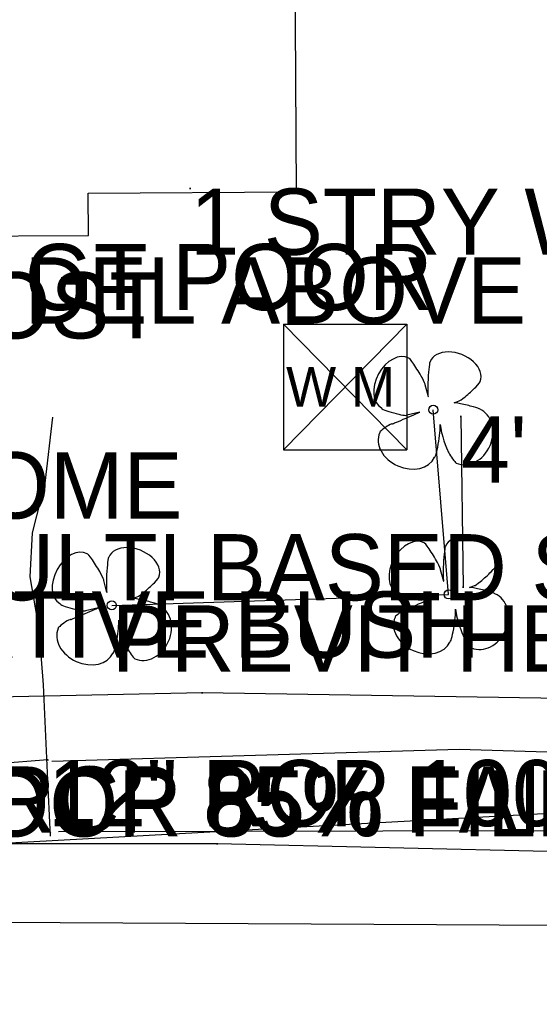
# Model space of a CAD drawing. Extents: x 1304270 to 1306561, y 1876019 to 1876752.
# Drawn here: x 1305385.4 to 1305424.7, y 1876408.6 to 1876482.3 of the extents above; entities that cross this region are included whole.
import ezdxf

# ---------------------------------------------------------------- set-up
doc = ezdxf.new("R2010")
doc.units = 0
for name, color, linetype in [('Default', 7, 'Continuous'), ('S_BUILDING', 7, 'Continuous'), ('S_BUILDING_ANNOT', 7, 'Continuous'), ('S_CROSS_DRAIN_ANNOT', 7, 'Continuous'), ('S_DITCHLINE', 7, 'Continuous'), ('S_DRG_PT_SYM', 7, 'Continuous'), ('S_EDGE_PAVEMENT', 7, 'Continuous'), ('S_FENCE', 7, 'Continuous'), ('S_FENCE_ANNOT', 7, 'Continuous'), ('S_FIBER_OPTIC_CABLE', 7, 'Continuous'), ('S_GATE_ANNOT', 7, 'Continuous'), ('S_MSC_PT_SYM', 7, 'Continuous'), ('S_SANITARY_SEWER', 7, 'Continuous'), ('S_SIDE_DRAIN', 7, 'Continuous'), ('S_SIDE_DRAIN_ANNOT', 7, 'Continuous'), ('S_SIDEWALK', 7, 'Continuous'), ('S_STR_PT_SYM', 7, 'Continuous'), ('S_SURVEY_TEXT_ANNOT', 7, 'Continuous'), ('S_TREE', 7, 'Continuous'), ('S_TREE_ANNOT', 7, 'Continuous'), ('S_UTL_PT_SYM', 7, 'Continuous'), ('S_WATER_UTILITIES', 7, 'Continuous')]:
    doc.layers.add(name, color=color, linetype=linetype)

msp = doc.modelspace()

# ---------------------------------------------------------------- linework, layer by layer
at = {"layer": 'Default'}
msp.add_line((1304873.941, 1876392.06), (1305473.534, 1876424.943), dxfattribs=at)
at = {"layer": 'S_BUILDING'}
msp.add_lwpolyline([(1305368.981, 1876540.96), (1305369.42, 1876465.829), (1305390.641, 1876465.953), (1305390.622, 1876469.145), (1305406.361, 1876469.237), (1305406.162, 1876503.401), (1305404.582, 1876503.391), (1305404.464, 1876523.501), (1305389.075, 1876523.411), (1305389.062, 1876525.646), (1305391.411, 1876525.659), (1305391.321, 1876541.09)], close=True, dxfattribs=at)
at = {"layer": 'S_DITCHLINE'}
msp.add_lwpolyline([(1305387.882, 1876426.25), (1305403.275, 1876426.705), (1305418.668, 1876427.159), (1305432.814, 1876426.73), (1305446.961, 1876426.301), (1305463.399, 1876426.578)], dxfattribs=at)
at = {"layer": 'S_DRG_PT_SYM'}
msp.add_lwpolyline([(1305387.576, 1876426.332), (1305387.576, 1876426.382), (1305387.576, 1876426.332), (1305387.526, 1876426.332), (1305387.576, 1876426.332), (1305387.576, 1876426.282), (1305387.576, 1876426.332), (1305387.626, 1876426.332)], dxfattribs=at)
at = {"layer": 'S_EDGE_PAVEMENT'}
msp.add_lwpolyline([(1305388.378, 1876420.939), (1305412.897, 1876420.988), (1305437.415, 1876421.038), (1305451.624, 1876420.928), (1305465.147, 1876420.967), (1305478.669, 1876421.007), (1305492.191, 1876421.046), (1305505.714, 1876421.086), (1305520.113, 1876421.199), (1305523.535, 1876421.95), (1305534.758, 1876421.533), (1305559.321, 1876421.957), (1305583.883, 1876422.381), (1305606.664, 1876422.73)], dxfattribs=at)
at = {"layer": 'S_FENCE'}
msp.add_line((1305418.785, 1876452.279), (1305418.96, 1876439.388), dxfattribs=at)
msp.add_lwpolyline([(1305418.785, 1876452.279), (1305418.96, 1876439.388)], dxfattribs=at)
msp.add_lwpolyline([(1305418.785, 1876452.279), (1305418.96, 1876439.388)], dxfattribs=at)
at = {"layer": 'S_FIBER_OPTIC_CABLE'}
for p, q in [((1305399.243, 1876431.395), (1305371.496, 1876430.825)), ((1305427.49, 1876430.961), (1305399.243, 1876431.395))]:
    msp.add_line(p, q, dxfattribs=at)
at = {"layer": 'S_MSC_PT_SYM'}
for points in [[(1305418.785, 1876452.279), (1305418.785, 1876452.329), (1305418.785, 1876452.279), (1305418.735, 1876452.279), (1305418.785, 1876452.279), (1305418.785, 1876452.229), (1305418.785, 1876452.279), (1305418.835, 1876452.279)], [(1305418.96, 1876439.388), (1305418.96, 1876439.438), (1305418.96, 1876439.388), (1305418.91, 1876439.388), (1305418.96, 1876439.388), (1305418.96, 1876439.338), (1305418.96, 1876439.388), (1305419.01, 1876439.388)]]:
    msp.add_lwpolyline(points, dxfattribs=at)
at = {"layer": 'S_SANITARY_SEWER'}
msp.add_line((1305626.325, 1876412.772), (1305348.539, 1876414.259), dxfattribs=at)
at = {"layer": 'S_SIDE_DRAIN'}
msp.add_line((1305387.576, 1876426.332), (1305383.624, 1876426.023), dxfattribs=at)
at = {"layer": 'S_SIDEWALK'}
msp.add_lwpolyline([(1305387.939, 1876452.224), (1305387.347, 1876447.245), (1305386.405, 1876443.475), (1305386.218, 1876440.154), (1305386.908, 1876436.209), (1305387.222, 1876432.013), (1305387.604, 1876423.689), (1305387.745, 1876420.591)], dxfattribs=at)
at = {"layer": 'S_STR_PT_SYM'}
msp.add_lwpolyline([(1305398.322, 1876469.49), (1305398.322, 1876469.54), (1305398.322, 1876469.49), (1305398.272, 1876469.49), (1305398.322, 1876469.49), (1305398.322, 1876469.44), (1305398.322, 1876469.49), (1305398.372, 1876469.49)], dxfattribs=at)
at = {"layer": 'S_TREE'}
for p, q in [((1305416.333, 1876453.762), (1305416.089, 1876454.655)), ((1305418.281, 1876453.302), (1305418.659, 1876453.464)), ((1305415.683, 1876452.599), (1305414.709, 1876452.382)), ((1305417.861, 1876438.832), (1305416.7, 1876452.782)), ((1305417.218, 1876451.668), (1305417.296, 1876451.229)), ((1305417.494, 1876439.812), (1305417.25, 1876440.705)), ((1305392.045, 1876438.988), (1305391.801, 1876439.881)), ((1305419.442, 1876439.352), (1305419.82, 1876439.514)), ((1305392.412, 1876438.008), (1305417.861, 1876438.832)), ((1305393.993, 1876438.528), (1305394.371, 1876438.69)), ((1305416.844, 1876438.649), (1305415.87, 1876438.432)), ((1305391.395, 1876437.824), (1305390.421, 1876437.608)), ((1305418.379, 1876437.718), (1305418.457, 1876437.279)), ((1305392.93, 1876436.894), (1305393.008, 1876436.455))]:
    msp.add_line(p, q, dxfattribs=at)
for centre in [(1305416.7, 1876452.782), (1305417.861, 1876438.832), (1305392.412, 1876438.008)]:
    msp.add_circle(centre, 0.341, dxfattribs=at)
for centre, major_axis, ratio, start_param, end_param in [((1305413.813, 1876454.8), (-1.031, -1.884), 0.662338, 3.141593, 6.283185), ((1305415.467, 1876455.669), (0.622, -1.015), 0.083512, 0, 3.141593), ((1305418.362, 1876455.669), (1.894, -0.744), 0.673998, 0, 3.141593), ((1305416.4, 1876455.088), (-0.068, -1.326), 0.068203, 3.141593, 6.283185), ((1305419.457, 1876454.195), (-0.798, -0.73), 0.092159, 0, 3.141593), ((1305419.241, 1876453.072), (0.96, -0.23), 0.056001, 0, 3.141593), ((1305413.745, 1876452.649), (0.964, -0.267), 0.113563, 3.141593, 6.283185), ((1305414.645, 1876452.156), (1.038, 0.443), 0.002756, 3.141593, 6.283185), ((1305419.319, 1876450.796), (0.883, 2.046), 0.81717, 3.141593, 6.283185), ((1305413.13, 1876451.385), (0.477, 0.328), 0.136309, 0, 3.141593), ((1305416.982, 1876450.502), (0.189, 1.312), 0.114148, 3.141593, 5.822668), ((1305414.723, 1876450.123), (2.07, -0.933), 0.760068, 3.141593, 6.283185), ((1305417.55, 1876450.458), (0.254, -0.771), 0.051603, 3.141593, 6.283185), ((1305418.125, 1876449.22), (-0.321, 0.467), 0.094289, 0, 3.141593), ((1305414.974, 1876440.85), (-1.031, -1.884), 0.662338, 3.141593, 6.283185), ((1305416.628, 1876441.719), (0.622, -1.015), 0.083512, 0, 3.141593), ((1305419.523, 1876441.719), (1.894, -0.744), 0.673998, 0, 3.141593), ((1305389.525, 1876440.026), (-1.031, -1.884), 0.662338, 3.141593, 6.283185), ((1305391.179, 1876440.895), (0.622, -1.015), 0.083512, 0, 3.141593), ((1305394.074, 1876440.895), (1.894, -0.744), 0.673998, 0, 3.141593), ((1305417.561, 1876441.138), (-0.068, -1.326), 0.068203, 3.141593, 6.283185), ((1305392.112, 1876440.314), (-0.068, -1.326), 0.068203, 3.141593, 6.283185), ((1305420.619, 1876440.245), (-0.798, -0.73), 0.092159, 0, 3.141593), ((1305395.169, 1876439.421), (-0.798, -0.73), 0.092159, 0, 3.141593), ((1305420.402, 1876439.122), (0.96, -0.23), 0.056001, 0, 3.141593), ((1305394.953, 1876438.298), (0.96, -0.23), 0.056001, 0, 3.141593), ((1305414.907, 1876438.699), (0.964, -0.267), 0.113563, 3.141593, 6.283185), ((1305415.806, 1876438.206), (1.038, 0.443), 0.002756, 3.141593, 6.283185), ((1305420.48, 1876436.846), (0.883, 2.046), 0.81717, 3.141593, 6.283185), ((1305389.457, 1876437.875), (0.964, -0.267), 0.113563, 3.141593, 6.283185), ((1305390.357, 1876437.381), (1.038, 0.443), 0.002756, 3.141593, 6.283185), ((1305395.031, 1876436.022), (0.883, 2.046), 0.81717, 3.141593, 6.283185), ((1305414.291, 1876437.434), (0.477, 0.328), 0.136309, 0, 3.141593), ((1305418.143, 1876436.552), (0.189, 1.312), 0.114148, 3.141593, 5.822668), ((1305388.842, 1876436.61), (0.477, 0.328), 0.136309, 0, 3.141593), ((1305392.694, 1876435.728), (0.189, 1.312), 0.114148, 3.141593, 5.822668), ((1305415.884, 1876436.173), (2.07, -0.933), 0.760068, 3.141593, 6.283185), ((1305418.711, 1876436.508), (0.254, -0.771), 0.051603, 3.141593, 6.283185), ((1305390.435, 1876435.349), (2.07, -0.933), 0.760068, 3.141593, 6.283185), ((1305393.262, 1876435.684), (0.254, -0.771), 0.051603, 3.141593, 6.283185), ((1305419.286, 1876435.27), (-0.321, 0.467), 0.094289, 0, 3.141593), ((1305393.837, 1876434.446), (-0.321, 0.467), 0.094289, 0, 3.141593)]:
    msp.add_ellipse(centre, major_axis=major_axis, ratio=ratio, start_param=start_param, end_param=end_param, dxfattribs=at)
at = {"layer": 'S_UTL_PT_SYM'}
for points in [[(1305399.243, 1876431.395), (1305399.243, 1876431.445), (1305399.243, 1876431.395), (1305399.193, 1876431.395), (1305399.243, 1876431.395), (1305399.243, 1876431.345), (1305399.243, 1876431.395), (1305399.293, 1876431.395)], [(1305400.373, 1876420.004), (1305400.373, 1876420.054), (1305400.373, 1876420.004), (1305400.323, 1876420.004), (1305400.373, 1876420.004), (1305400.373, 1876419.954), (1305400.373, 1876420.004), (1305400.423, 1876420.004)]]:
    msp.add_lwpolyline(points, dxfattribs=at)
at = {"layer": 'S_WATER_UTILITIES'}
for p, q in [((1305405.373, 1876459.254), (1305414.712, 1876459.254)), ((1305405.373, 1876459.254), (1305405.373, 1876449.76)), ((1305405.373, 1876459.254), (1305414.712, 1876449.76)), ((1305414.712, 1876459.254), (1305405.373, 1876449.76)), ((1305414.712, 1876459.254), (1305414.712, 1876449.76)), ((1305405.373, 1876449.76), (1305414.712, 1876449.76)), ((1305400.373, 1876420.004), (1305362.843, 1876419.995)), ((1305462.853, 1876418.517), (1305400.373, 1876420.004))]:
    msp.add_line(p, q, dxfattribs=at)

# ---------------------------------------------------------------- texts
at = {"layer": 'S_BUILDING_ANNOT'}
msp.add_text('1 STRY WOOD', height=5, dxfattribs=at).set_placement((1305398.322, 1876464.49))
at = {"layer": 'S_CROSS_DRAIN_ANNOT'}
msp.add_text('12" RCP POOR 85% FILL 24.23', height=5, dxfattribs=at).set_placement((1305350.386, 1876420.555))
at = {"layer": 'S_FENCE_ANNOT'}
for s, p in [("5' CHAINLINK MTL POST", (1305318.506, 1876458.169)), ("4' CHAINLINK MTL POST GOOD", (1305418.785, 1876447.279))]:
    msp.add_text(s, height=5, dxfattribs=at).set_placement(p)
at = {"layer": 'S_GATE_ANNOT'}
msp.add_text("5' 3' CHAINLINK MTL GT POOR", height=5, dxfattribs=at).set_placement((1305319.368, 1876460.305))
at = {"layer": 'S_SIDE_DRAIN_ANNOT'}
for s, p in [('12" RCP 25% FAIR DEL ABOVE SHOTS 4.21', (1305325.836, 1876459.292)), ('12" RCP 85% FAIR 16.17', (1305371.658, 1876420.843)), ('12" RCP 100% POOR 3.95', (1305387.576, 1876421.332))]:
    msp.add_text(s, height=5, dxfattribs=at).set_placement(p)
at = {"layer": 'S_SURVEY_TEXT_ANNOT'}
msp.add_text('1 STRY WOOD ABANDON BU/HOME', height=5, dxfattribs=at).set_placement((1305282.963, 1876444.567))
at = {"layer": 'S_TREE_ANNOT'}
for s, p in [('MULTI BASED SR', (1305377.677, 1876438.389)), ('DECORATIVE BUSH', (1305356.333, 1876434.058)), ('PREVIT HEDGE', (1305392.412, 1876433.008))]:
    msp.add_text(s, height=5, dxfattribs=at).set_placement(p)
at = {"layer": 'S_WATER_UTILITIES'}
msp.add_text('W M', height=3, rotation=360, dxfattribs=at).set_placement((1305405.578, 1876453.02))

doc.saveas('drawing.dxf')
